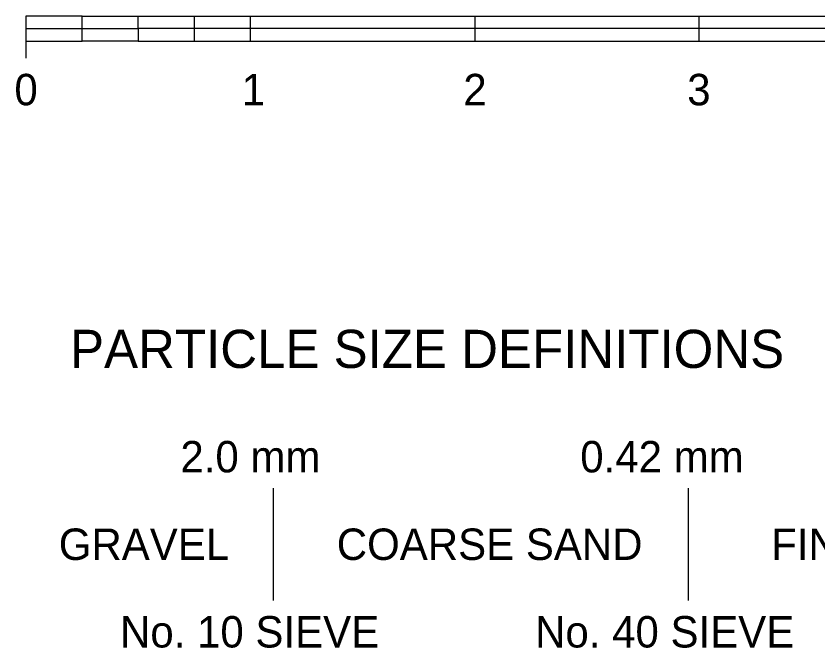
# Model space of a CAD drawing. Extents: x -13.7 to 34, y 0 to 32.3.
# Drawn here: x 24.872 to 28.447, y 10.405 to 13.22 of the extents above; entities that cross this region are included whole.
import ezdxf

# ---------------------------------------------------------------- set-up
doc = ezdxf.new("R2010")
doc.units = 0
doc.layers.add('SH_Data', color=7, linetype='Continuous')
doc.layers.add('SH_Text', color=7, linetype='Continuous')

msp = doc.modelspace()

# ---------------------------------------------------------------- linework, layer by layer
at = {"layer": 'SH_Data'}
for p, q in [((25.1667, 13.22), (24.9167, 13.22)), ((24.9167, 13.22), (24.9167, 13.1638)), ((25.1667, 13.22), (25.4167, 13.22)), ((25.1667, 13.1638), (25.1667, 13.22)), ((25.4167, 13.1638), (25.4167, 13.22)), ((25.4167, 13.22), (25.6667, 13.22)), ((25.6667, 13.22), (25.9167, 13.22)), ((25.6667, 13.22), (25.6667, 13.1638)), ((25.9167, 13.1638), (25.9167, 13.22)), ((25.9167, 13.22), (26.9167, 13.22)), ((26.9167, 13.22), (26.9167, 13.1638)), ((26.9167, 13.22), (27.9167, 13.22)), ((27.9167, 13.1638), (27.9167, 13.22)), ((27.9167, 13.22), (28.9167, 13.22)), ((24.9167, 13.1638), (24.9167, 13.0325)), ((24.9167, 13.1638), (25.1667, 13.1638)), ((25.1667, 13.1638), (25.4167, 13.1638)), ((25.1667, 13.1075), (25.1667, 13.1638)), ((25.4167, 13.1638), (25.4167, 13.1075)), ((25.6667, 13.1638), (25.4167, 13.1638)), ((25.9167, 13.1638), (25.6667, 13.1638)), ((25.6667, 13.1638), (25.6667, 13.1075)), ((25.9167, 13.1075), (25.9167, 13.1638)), ((26.9167, 13.1638), (25.9167, 13.1638)), ((27.9167, 13.1638), (26.9167, 13.1638)), ((26.9167, 13.1638), (26.9167, 13.1075)), ((27.9167, 13.1075), (27.9167, 13.1638)), ((28.9167, 13.1638), (27.9167, 13.1638)), ((24.9167, 13.1075), (25.1667, 13.1075)), ((25.4167, 13.1075), (25.1667, 13.1075)), ((25.4167, 13.1075), (25.6667, 13.1075)), ((25.6667, 13.1075), (25.9167, 13.1075)), ((25.9167, 13.1075), (26.9167, 13.1075)), ((26.9167, 13.1075), (27.9167, 13.1075)), ((27.9167, 13.1075), (28.9167, 13.1075)), ((26.0196, 10.6173), (26.0196, 11.1173)), ((27.8696, 10.6173), (27.8696, 11.1173))]:
    msp.add_line(p, q, dxfattribs=at)

# ---------------------------------------------------------------- texts
at = {"layer": 'SH_Text'}
for s, height, p in [('0', 0.14, (24.8651, 12.8225)), ('1', 0.14, (25.8782, 12.8225)), ('2', 0.14, (26.866, 12.8225)), ('3', 0.14, (27.8639, 12.8225)), ('PARTICLE SIZE DEFINITIONS', 0.17, (25.113, 11.6525)), ('2.0 mm', 0.14, (25.6049, 11.1873)), ('0.42 mm', 0.14, (27.3872, 11.1873)), ('GRAVEL', 0.14, (25.0628, 10.7973)), ('COARSE SAND', 0.14, (26.3019, 10.7973)), ('FINE SAND', 0.14, (28.238, 10.7973)), ('No. 10 SIEVE', 0.14, (25.3358, 10.4073)), ('No. 40 SIEVE', 0.14, (27.1858, 10.4073))]:
    msp.add_text(s, height=height, dxfattribs=at).set_placement(p)

doc.saveas('drawing.dxf')
